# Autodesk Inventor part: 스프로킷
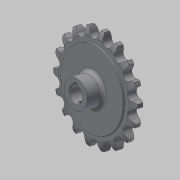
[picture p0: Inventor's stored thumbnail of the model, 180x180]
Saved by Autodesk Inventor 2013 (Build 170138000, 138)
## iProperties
Created: 2016-03
Part Number: 스프로킷
Material: 강철, 탄소
Document SubType Name: Modeling
Designer: mduedu
Density: 7.87 g/cm^3
Mass: 301.836 g
Surface Area: 124.883 cm^2
Volume: 38.3528 cm^3
Author: mduedu
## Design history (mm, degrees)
sketch "스케치1"
  geometry: L1 (0, 5)-(29.5, 5); L2 (29.5, 5)-(29.5, 4.1); L3 (30, 3.6)-(33.625, 3.6); L4 (40, 2)-(40, 0); L5 (40, 0)-(0, 0); L6 (0, 0)-(0, 5); L7 (0, -5)-(29.5, -5); L8 (29.5, -5)-(29.5, -4.1); L9 (30, -3.6)-(33.625, -3.6); L10 (40, -2)-(40, 0); L11 (0, 0)-(0, -5); A1 r 13.5 centre (33.625, -9.9) between (40, 2) and (33.625, 3.6); A2 r 13.5 centre (33.625, 9.9) between (33.625, -3.6) and (40, -2); A3 r 0.5 centre (30, 4.1) between (29.5, 4.1) and (30, 3.6); A4 r 0.5 centre (30, -4.1) between (30, -3.6) and (29.5, -4.1); 2 further points
  constraints: 22 end point, 8 point on circle, 6 symmetric about line, 5 tangent, 4 centre point, 4 parallel, 4 point on line, 1 equal radius, 1 horizontal, 1 perpendicular, 1 other
  dimensions: "d0" = 80 diameter of L4 L6; "d2" = 59 diameter of L2 L6; "d3" = 1.6 vertical distance of L4.start L3.end; "d4" = 3.6 distance from line of L4.end L3; "d5" = 5 distance between parallel lines of L5 L1; "d6" = 13.5 radius of A1; "d15" = 0.5 radius of A3
revolve "회전1" sketch "스케치1" stored, may be unused: angle "d7" = 90 deg
sketch "스케치2" dims "d8" = 65.2, "d11" = 80
  geometry: L1 (0, 0)-(0, 32.6); A1 r 36.57 centre (0, 0) between (-16.231, 32.771) and (0, 36.57); A2 r 3.97 centre (0, 36.57) between (-3.866, 35.665) and (0, 32.6); A3 r 12.7 centre (-16.231, 32.771) between (-3.866, 35.665) and (-5.534, 39.615); A4 r 12.7 centre (16.231, 32.771) between (5.534, 39.615) and (3.866, 35.665); A5 r 3.97 centre (0, 36.57) between (0, 32.6) and (3.866, 35.665); A6 r 40 centre (0, 0) between (5.534, 39.615) and (-5.534, 39.615); 2 further points
  constraints: 12 point on circle, 6 centre point, 4 coincident, 3 symmetric about line, 2 end point, 1 point on line, 1 tangent, 1 vertical, 1 vertical alignment, 7 other
  dimensions: "d10" = 73.14 diameter of A1; "d12" = 12.7 radius of A3
extrude "돌출1" cut sketch "스케치2" stored distance "d13" = 10; taper "d14" = 0 deg
sketch "스케치3"
  geometry: C1 r 11 at (0, 0); 1 further point
  constraints: 1 centre point, 1 coincident
  dimensions: "d19" = 22 diameter of C1
extrude "돌출2" join sketch "스케치3" distance "d20" = 13; taper "d21" = 0 deg
fillet "모깎기1" dims "d22" = 3
sketch "스케치4"
  geometry: L1 (-2, 0)-(2, 0); L2 (2, 0)-(2, 7.8); L3 (2, 7.8)-(-2, 7.8); L4 (-2, 7.8)-(-2, 0); C1 r 6 at (0, 0); 2 further points
  constraints: 8 end point, 2 coincident, 2 parallel, 1 centre point, 1 horizontal, 1 midpoint, 1 perpendicular
  dimensions: "d23" = 12 diameter of C1; "d25" = 4 distance of L2.end L3.end; "d26" = 7.8 distance of L1.end L2.end
extrude "돌출3" cut sketch "스케치4" stored distance "d27" = 8; taper "d28" = 0 deg
chamfer "모따기1" distance "d29" = 0.5; stored, may be unused: second distance "d30" = 2, angle "d31" = 45 deg
node "작업 평면1"
sketch "스케치5"
  geometry: L1 (11, 13)-(-11, 13) reference; 2 further points
  constraints: 1 vertical alignment
  dimensions: "d32" = 4 distance from line of point (0, 9) L1
hole "구멍1" sketch "스케치5" at (0, 9) diameter "d33" = 2.459; stored, may be unused: countersink angle "d37" = 90 deg, drill point angle "d39" = 118 deg; dims "d34" = 6, "d35" = 4, "d36" = 2, "d38" = 8
node "솔리드1"
pattern_circular "원형 패턴1" dims angle "d17" = 360 deg
